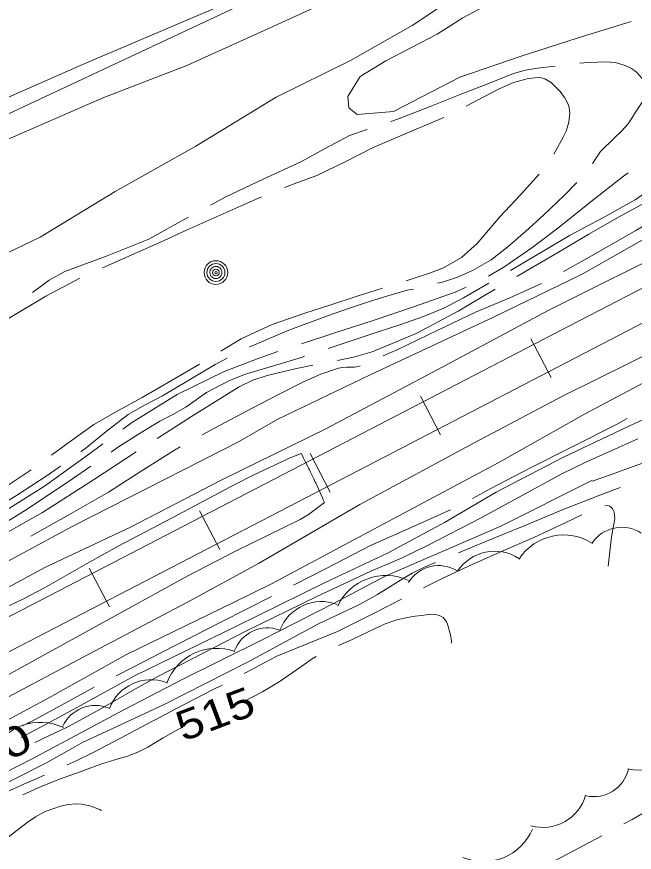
# Model space of a CAD drawing. Extents: x 2361284 to 2366480, y 6976556 to 6985346.
# Drawn here: x 2364083.1 to 2364182.3, y 6978587.5 to 6978721.9 of the extents above; entities that cross this region are included whole.
import ezdxf
from ezdxf.enums import TextEntityAlignment as Align

# ---------------------------------------------------------------- set-up
doc = ezdxf.new("R2010")
doc.units = 0
doc.header["$LTSCALE"] = 1.9
for name, color, linetype, lineweight in [('12', 7, 'Continuous', 13), ('13', 7, 'Continuous', 13), ('15', 7, 'Continuous', 13), ('16', 7, 'Continuous', 13), ('20', 7, 'Continuous', 13), ('22', 7, 'Continuous', 13), ('29', 7, 'Continuous', 13), ('3', 7, 'Continuous', 13), ('4', 7, 'Continuous', 13)]:
    doc.layers.add(name, color=color, linetype=linetype, lineweight=lineweight)

msp = doc.modelspace()

# ---------------------------------------------------------------- linework, layer by layer
at = {"layer": '12'}
msp.add_lwpolyline([(2364083.777, 6978605.938), (2364089.996, 6978609.258), (2364102.074, 6978615.943), (2364118.289, 6978623.778), (2364132.662, 6978630.886), (2364142.678, 6978635.59), (2364151.802, 6978640.557), (2364160.135, 6978645.426), (2364170.933, 6978651.06), (2364182.343, 6978656.449), (2364195.668, 6978662.296), (2364208.403, 6978668.106), (2364217.26, 6978673.692)], dxfattribs=at)
at = {"layer": '13'}
for points in [[(2364316.907, 6978749.303), (2364313.473, 6978747.58), (2364304.173, 6978743.362), (2364291.676, 6978737.742), (2364273.995, 6978728.114), (2364260.412, 6978721.104), (2364242.99, 6978711.738), (2364226.685, 6978703.713), (2364208.352, 6978694.457), (2364190.207, 6978685.475), (2364168.479, 6978674.628), (2364150.769, 6978665.128), (2364132.758, 6978655.598), (2364116.035, 6978647.397), (2364101.248, 6978639.726), (2364087.697, 6978633.368), (2364076.324, 6978627.239), (2364064.329, 6978621.474), (2364055.005, 6978617.546), (2364048.402, 6978614.643), (2364040.227, 6978611.065), (2364032.027, 6978606.637)], [(2364320.846, 6978741.031), (2364317.59, 6978739.54), (2364310.146, 6978735.718), (2364301.969, 6978731.13), (2364295.123, 6978727.505), (2364285.873, 6978722.206), (2364276.399, 6978717.277), (2364262.941, 6978709.688), (2364252.425, 6978703.897), (2364240.292, 6978696.902), (2364227.251, 6978690.538), (2364214.992, 6978683.981), (2364202.477, 6978677.171), (2364186.695, 6978668.74), (2364170.8, 6978660.879), (2364156.681, 6978653.385), (2364138.204, 6978643.408), (2364121.923, 6978633.953), (2364110.521, 6978627.734), (2364094.521, 6978619.291), (2364075.604, 6978609.261), (2364063.636, 6978602.807), (2364048.497, 6978595.203), (2364040.513, 6978590.407)], [(2364271.539, 6978729.88), (2364252.804, 6978721.862), (2364234.916, 6978714.261), (2364211.606, 6978701.559), (2364192.514, 6978691.066), (2364173.944, 6978680.48), (2364159.698, 6978673.554), (2364139.756, 6978664.253), (2364125.053, 6978657.144), (2364118.707, 6978653.514), (2364104.067, 6978646.083), (2364092.095, 6978639.919), (2364081.369, 6978634.147), (2364067.98, 6978626.579), (2364056.145, 6978619.746), (2364051.183, 6978617.739), (2364044.277, 6978615.273), (2364038.087, 6978612.114), (2364031.238, 6978607.659)], [(2364138.539, 6978726.956), (2364125.687, 6978720.973), (2364110.391, 6978714.068), (2364097.079, 6978708.901), (2364080.018, 6978701.528), (2364064.988, 6978693.054), (2364045.989, 6978686.494), (2364033.041, 6978680.931), (2364026.961, 6978677.803), (2364011.93, 6978671.578), (2364001.985, 6978665.624), (2363992.21, 6978660.91)], [(2364301.264, 6978725.323), (2364290.21, 6978719.437), (2364278.454, 6978712.585), (2364264.992, 6978705.397), (2364245.94, 6978695.915), (2364230.683, 6978687.12), (2364211.127, 6978677.274), (2364191.552, 6978667.116), (2364174.308, 6978657.983), (2364160.441, 6978650.12), (2364138.84, 6978638.584), (2364124.005, 6978630.643), (2364117.793, 6978627.583), (2364100.712, 6978619.27), (2364088.197, 6978612.321), (2364078.027, 6978606.854), (2364068.178, 6978601.63), (2364061.939, 6978598.331), (2364053.285, 6978594.358)], [(2364162.082, 6978725.72), (2364154.781, 6978721.75), (2364150.646, 6978719.1), (2364142.365, 6978714.802), (2364138.239, 6978712.302), (2364136.289, 6978709.064), (2364136.417, 6978707.245), (2364137.797, 6978706.158), (2364143.642, 6978706.683), (2364154.292, 6978712.175), (2364163.979, 6978715.497), (2364173.133, 6978718.454), (2364181.838, 6978721.117)], [(2363990.169, 6978666.251), (2363998.65, 6978670.392), (2364009.081, 6978675.623), (2364018.458, 6978680.122), (2364028.992, 6978685.072), (2364041.462, 6978690.48), (2364054.213, 6978696.613), (2364060.696, 6978699.584), (2364070.861, 6978704.321), (2364081.28, 6978708.761), (2364093.539, 6978714.197), (2364108.997, 6978720.775), (2364118.22, 6978724.732)], [(2364081.556, 6978683.942), (2364086.852, 6978686.462), (2364098.903, 6978693.806), (2364111.844, 6978701.071), (2364124.741, 6978708.964), (2364136.704, 6978714.878), (2364146.632, 6978720.522), (2364151.203, 6978723.546)], [(2364085.975, 6978605.119), (2364091.252, 6978607.64), (2364096.11, 6978610.302), (2364102.506, 6978614.002), (2364105.745, 6978615.778), (2364119.886, 6978623.063), (2364131.284, 6978628.642), (2364139.965, 6978632.715), (2364144.887, 6978634.801), (2364149.194, 6978636.885), (2364157.696, 6978641.273), (2364170.57, 6978648.306), (2364174.622, 6978650.313), (2364182.896, 6978653.974)], [(2364128.756, 6978651.649), (2364127.023, 6978650.923), (2364121.043, 6978648.145), (2364118.102, 6978646.657), (2364108.162, 6978641.352), (2364099.355, 6978636.728), (2364094.254, 6978633.892), (2364087.5, 6978630.023), (2364084.066, 6978628.193), (2364079.15, 6978625.868), (2364072.514, 6978622.938), (2364069.23, 6978621.401), (2364057.753, 6978615.772), (2364045.141, 6978609.641), (2364041.156, 6978607.882), (2364038.449, 6978606.828), (2364032.964, 6978604.875)], [(2364132.51, 6978643.754), (2364132.322, 6978644.192), (2364132.196, 6978644.484), (2364131.941, 6978645.066), (2364131.812, 6978645.356), (2364131.552, 6978645.936), (2364131.289, 6978646.514), (2364131.111, 6978646.899), (2364130.992, 6978647.155), (2364130.753, 6978647.667), (2364130.541, 6978648.114), (2364130.398, 6978648.412), (2364130.302, 6978648.61), (2364130.108, 6978649.005), (2364129.962, 6978649.301), (2364129.864, 6978649.497), (2364129.666, 6978649.89), (2364129.366, 6978650.478), (2364129.164, 6978650.869), (2364129.029, 6978651.129), (2364128.756, 6978651.649)], [(2364042.263, 6978586.203), (2364043.908, 6978584.609), (2364047.058, 6978584.569), (2364053.349, 6978586.588), (2364060.968, 6978589.991), (2364067.641, 6978593.895), (2364073.966, 6978596.585), (2364085.53, 6978602.525), (2364100.286, 6978610.396), (2364109.839, 6978615.367), (2364122.301, 6978621.526), (2364134.064, 6978627.578), (2364142.174, 6978631.826), (2364160.898, 6978639.943), (2364175.49, 6978647.282)], [(2364132.51, 6978643.754), (2364129.975, 6978641.846), (2364128.617, 6978641.037), (2364118.094, 6978635.866), (2364110.581, 6978631.956), (2364099.946, 6978626.123), (2364087.183, 6978619.062), (2364076.129, 6978612.946), (2364071.277, 6978610.53), (2364064.642, 6978607.635), (2364061.344, 6978606.145), (2364054.101, 6978602.645), (2364050.514, 6978600.812), (2364046.548, 6978598.514), (2364043.999, 6978596.829), (2364039.046, 6978593.223)], [(2364040.349, 6978584.585), (2364041.366, 6978583.823), (2364044.159, 6978583.48), (2364051.251, 6978584.218), (2364058.424, 6978587.217), (2364064.973, 6978590.539), (2364070.255, 6978593.529), (2364077.415, 6978596.588), (2364087.737, 6978601.836), (2364093.655, 6978605.152), (2364106.768, 6978611.257), (2364120.233, 6978618.106), (2364131.446, 6978624.173), (2364138.156, 6978627.337)], [(2364085.443, 6978608.535), (2364085.327, 6978608.477), (2364085.172, 6978608.4), (2364085.094, 6978608.361), (2364085.052, 6978608.34), (2364084.969, 6978608.299), (2364084.885, 6978608.259), (2364084.829, 6978608.232), (2364084.792, 6978608.214), (2364084.742, 6978608.19), (2364084.717, 6978608.178), (2364084.661, 6978608.152), (2364084.549, 6978608.099), (2364084.324, 6978607.993), (2364084.212, 6978607.94), (2364084.1, 6978607.887), (2364084.044, 6978607.86), (2364083.96, 6978607.82)]]:
    msp.add_lwpolyline(points, dxfattribs=at)
at = {"layer": '15'}
for points in [[(2364197.95, 6978602.084), (2364196.131, 6978600.987), (2364182.008, 6978592.752), (2364180.665, 6978592.029)], [(2364177.133, 6978590.145), (2364167.322, 6978584.922), (2364159.379, 6978580.935)]]:
    msp.add_lwpolyline(points, dxfattribs=at)
at = {"layer": '16'}
for centre, radius, start, end in [((2364180.301, 6978634.068), 5.694, 56.68024, 146.68024), ((2364170.953, 6978629.982), 8.546, 56.83182, 146.83182), ((2364159.881, 6978628.785), 7.125, 56.83182, 146.83182), ((2364150.902, 6978627.908), 5.694, 58.58081, 148.58081), ((2364142.408, 6978623.465), 8.546, 64.9872, 154.9872), ((2364132.035, 6978620.682), 7.125, 69.29215, 159.29215), ((2364123.379, 6978617.874), 5.694, 69.94529, 159.94529), ((2364115.203, 6978611.748), 8.546, 69.94529, 159.94529), ((2364104.636, 6978608.109), 7.125, 69.5711, 159.5711), ((2364095.663, 6978605.407), 5.694, 66.6985, 156.6985), ((2364086.849, 6978599.843), 8.546, 64.33074, 154.33074), ((2364183.152, 6978609.24), 8.546, 257.31447, 347.31447), ((2364175.829, 6978602.116), 5.694, 257.31447, 347.31447), ((2364167.646, 6978598.596), 7.125, 254.08649, 344.08649), ((2364158.072, 6978594.518), 8.546, 247.21802, 337.21802)]:
    msp.add_arc(centre, radius, start, end, dxfattribs=at)
at = {"layer": '20'}
for points in [[(2364175.634, 6978698.297), (2364176.916, 6978700.229), (2364179.145, 6978702.431), (2364180.285, 6978703.502), (2364181.314, 6978704.681), (2364181.945, 6978705.587), (2364182.546, 6978706.533), (2364183.68, 6978708.304), (2364184.181, 6978709.189), (2364184.583, 6978710.073), (2364184.631, 6978710.313), (2364184.599, 6978710.533), (2364184.435, 6978710.911), (2364183.524, 6978712.043), (2364182.766, 6978712.906), (2364182.352, 6978713.262), (2364181.869, 6978713.577), (2364180.845, 6978714.067), (2364179.28, 6978714.543), (2364177.689, 6978714.677), (2364174.22, 6978714.494), (2364173.561, 6978714.418)], [(2364169.585, 6978713.98), (2364166.787, 6978713.654), (2364164.83, 6978713.325), (2364162.935, 6978712.757), (2364158.761, 6978711.117), (2364154.597, 6978709.478), (2364149.526, 6978707.469), (2364144.444, 6978705.471), (2364143.168, 6978705.049)], [(2364169.38, 6978699.788), (2364169.685, 6978700.271), (2364170.914, 6978702.542), (2364171.355, 6978703.497), (2364171.811, 6978704.961), (2364171.967, 6978706.413), (2364171.859, 6978707.302), (2364171.642, 6978707.96), (2364171.123, 6978708.915), (2364170.394, 6978709.868), (2364169.576, 6978710.75), (2364168.95, 6978711.314), (2364167.954, 6978711.935), (2364167.433, 6978712.1), (2364166.892, 6978712.155), (2364165.323, 6978711.99), (2364162.929, 6978711.307), (2364160.629, 6978710.305), (2364156.003, 6978707.871), (2364155.276, 6978707.504)], [(2364151.703, 6978705.71), (2364151.355, 6978705.537), (2364145.856, 6978703.204), (2364140.358, 6978700.852), (2364135.839, 6978698.579), (2364131.3, 6978696.346), (2364127.634, 6978695.001), (2364126.099, 6978694.435)], [(2364139.38, 6978703.763), (2364136.569, 6978702.786), (2364132.618, 6978700.728), (2364128.72, 6978698.571), (2364122.686, 6978695.754), (2364116.652, 6978692.935), (2364114.194, 6978691.592)], [(2364145.672, 6978679.431), (2364149.591, 6978680.679), (2364151.653, 6978681.498), (2364154.547, 6978683.186), (2364157.076, 6978685.4), (2364158.915, 6978687.548), (2364160.714, 6978689.705), (2364164.011, 6978693.265), (2364167.041, 6978696.555)], [(2364181.359, 6978696.801), (2364180.584, 6978696.264), (2364175.403, 6978692.174), (2364170.262, 6978688.026), (2364165.882, 6978684.744), (2364161.381, 6978681.621), (2364158.885, 6978680.157)], [(2364150.716, 6978679.039), (2364151.475, 6978679.217), (2364153.927, 6978680.03), (2364156.328, 6978681.053), (2364159.3, 6978682.811), (2364162.01, 6978684.907), (2364164.916, 6978687.415), (2364167.753, 6978689.982), (2364171.123, 6978693.193), (2364173.084, 6978695.233)], [(2364186.533, 6978695.271), (2364182.441, 6978692.431), (2364177.258, 6978689.562), (2364172.044, 6978686.752), (2364166.524, 6978683.51), (2364162.416, 6978681.091)], [(2364195.218, 6978694.843), (2364190.325, 6978692.016), (2364182.587, 6978687.533), (2364175.187, 6978683.272), (2364170.93, 6978680.912)], [(2364122.382, 6978692.95), (2364119.125, 6978691.509), (2364114.306, 6978689.344), (2364110.462, 6978687.597), (2364106.629, 6978685.84), (2364100.126, 6978682.949), (2364096.84, 6978681.487)], [(2364110.683, 6978689.668), (2364110.474, 6978689.557), (2364104.316, 6978686.119), (2364097.591, 6978683.434), (2364090.795, 6978680.94), (2364088.268, 6978679.506), (2364085.577, 6978677.55)], [(2364093.195, 6978679.832), (2364087.722, 6978676.96), (2364082.015, 6978673.526), (2364078.397, 6978671.17), (2364074.88, 6978668.667), (2364073.383, 6978667.383), (2364071.333, 6978665.223), (2364070.153, 6978664.182)], [(2364158.966, 6978679.068), (2364154.869, 6978676.659), (2364151.725, 6978675.019), (2364148.458, 6978673.658), (2364144.649, 6978672.36), (2364140.841, 6978671.094), (2364134.909, 6978669.128), (2364133.124, 6978668.541)], [(2364115.858, 6978668.106), (2364116.007, 6978668.198), (2364119.129, 6978670.088), (2364124.139, 6978672.375), (2364129.342, 6978674.196), (2364133.558, 6978675.566), (2364137.775, 6978676.936), (2364141.863, 6978678.225)], [(2364120.451, 6978668.8), (2364120.501, 6978668.821), (2364126.777, 6978671.47), (2364133.154, 6978673.852), (2364136.364, 6978674.963), (2364139.583, 6978676.043), (2364142.684, 6978677.013), (2364145.807, 6978677.903), (2364146.127, 6978677.956), (2364146.456, 6978678.009), (2364146.825, 6978678.102)], [(2364155.303, 6978678.393), (2364153.55, 6978677.616), (2364146.982, 6978675.274), (2364140.372, 6978673.041), (2364133.862, 6978670.938), (2364128.828, 6978669.3)], [(2364167.418, 6978678.998), (2364162.298, 6978676.689), (2364156.821, 6978674.387), (2364150.619, 6978671.427), (2364144.416, 6978668.448), (2364141.966, 6978667.325)], [(2364093.361, 6978651.933), (2364093.937, 6978652.348), (2364097.43, 6978655.192), (2364100.995, 6978657.926), (2364103.72, 6978659.442), (2364106.466, 6978660.908), (2364110.712, 6978663.427), (2364114.958, 6978665.938), (2364116.878, 6978666.996)], [(2364125.04, 6978668.024), (2364121.849, 6978666.923), (2364116.409, 6978664.822), (2364108.834, 6978661.12), (2364101.657, 6978656.672), (2364100.117, 6978655.537)], [(2364129.327, 6978667.274), (2364128.978, 6978667.161), (2364124.332, 6978665.737), (2364119.674, 6978664.323), (2364117.153, 6978663.349), (2364113.571, 6978661.445), (2364110.223, 6978659.083)], [(2364088.636, 6978651.348), (2364091.247, 6978653.323), (2364095.469, 6978656.323), (2364099.328, 6978658.51), (2364103.208, 6978660.647), (2364108.062, 6978663.452), (2364112.448, 6978666.004)], [(2364138.281, 6978665.76), (2364138.142, 6978665.698), (2364137.333, 6978665.52), (2364136.053, 6978665.508), (2364135.414, 6978665.482), (2364134.795, 6978665.366), (2364131.934, 6978664.399), (2364129.166, 6978663.193), (2364125.126, 6978661.135), (2364121.114, 6978659.047), (2364114.736, 6978655.656), (2364112.846, 6978654.628)], [(2364110.223, 6978659.083), (2364108.154, 6978657.924), (2364106.065, 6978656.814), (2364102.644, 6978654.721), (2364099.265, 6978652.579), (2364098.231, 6978651.869)], [(2364181.195, 6978657.258), (2364179.354, 6978656.271), (2364172.467, 6978652.755), (2364165.559, 6978649.288), (2364159.28, 6978645.978), (2364156.316, 6978644.42)], [(2364096.899, 6978653.166), (2364094.615, 6978651.485), (2364087.523, 6978646.386), (2364081.906, 6978642.842), (2364076.248, 6978639.359), (2364073.565, 6978637.733)], [(2364109.344, 6978652.705), (2364108.399, 6978652.186), (2364103.081, 6978648.804), (2364097.783, 6978645.404), (2364091.407, 6978641.763), (2364085.319, 6978638.345)], [(2364175.53, 6978647.193), (2364178.481, 6978648.221), (2364181.421, 6978649.259), (2364186.114, 6978650.935), (2364188.725, 6978651.88)], [(2364066.068, 6978635.292), (2364071.509, 6978638.363), (2364074.731, 6978640.074), (2364077.955, 6978641.805), (2364083.007, 6978644.873), (2364087.937, 6978648.12), (2364090.102, 6978649.621)], [(2364094.943, 6978649.597), (2364092.032, 6978647.579), (2364084.738, 6978642.659), (2364078.872, 6978639.063), (2364072.956, 6978635.537), (2364071.325, 6978634.582)], [(2364061.302, 6978634.836), (2364064.018, 6978636.272), (2364067.354, 6978637.824), (2364070.658, 6978639.455), (2364075.917, 6978642.696), (2364081.065, 6978646.115), (2364084.096, 6978648.154), (2364085.378, 6978649.026)], [(2364154.079, 6978635.638), (2364158.312, 6978637.399), (2364164.607, 6978640.019), (2364170.914, 6978642.629), (2364176.792, 6978644.915), (2364180.031, 6978646.146)], [(2364177.568, 6978643.232), (2364177.948, 6978643.266), (2364178.188, 6978643.228), (2364178.359, 6978643.15), (2364178.601, 6978642.982), (2364178.803, 6978642.734), (2364179.068, 6978642.186), (2364179.162, 6978641.777), (2364179.188, 6978641.157), (2364179.114, 6978640.537), (2364178.885, 6978639.394), (2364178.666, 6978638.242), (2364178.388, 6978635.869), (2364178.111, 6978633.498)], [(2364152.773, 6978642.566), (2364146.46, 6978639.746), (2364139.926, 6978636.824), (2364132.771, 6978633.137), (2364127.547, 6978630.447)], [(2364148.462, 6978630.016), (2364151.14, 6978631.351), (2364155.759, 6978633.575), (2364160.956, 6978635.884), (2364166.175, 6978638.133), (2364171.194, 6978640.481), (2364173.872, 6978641.757)], [(2364138.156, 6978627.337), (2364139.609, 6978628.151), (2364141.051, 6978628.965), (2364144.77, 6978631.281), (2364146.64, 6978632.408), (2364148.601, 6978633.367), (2364150.384, 6978634.103)], [(2364123.995, 6978628.623), (2364115.972, 6978624.526), (2364106.329, 6978619.604), (2364101.642, 6978617.209), (2364099.064, 6978615.884)], [(2364119.611, 6978616.23), (2364120.726, 6978616.81), (2364122.806, 6978617.93), (2364124.886, 6978619.04), (2364129.747, 6978621.026), (2364134.638, 6978622.973), (2364140.599, 6978626.02), (2364144.889, 6978628.212)], [(2364095.521, 6978614.021), (2364091.203, 6978611.659), (2364085.443, 6978608.535)], [(2364091.18, 6978601.549), (2364092.603, 6978602.212), (2364095.47, 6978603.6), (2364099.719, 6978605.839), (2364103.958, 6978608.081), (2364106.247, 6978609.282), (2364108.545, 6978610.474), (2364114.636, 6978613.642), (2364116.059, 6978614.386)], [(2364075.012, 6978593.715), (2364076.363, 6978594.678), (2364077.785, 6978595.521), (2364083.741, 6978598.228), (2364087.535, 6978599.904)], [(2364079.025, 6978588.263), (2364081.054, 6978589.422), (2364083.507, 6978591.285), (2364084.717, 6978592.277), (2364086.059, 6978593.19), (2364087.651, 6978594.025), (2364090.093, 6978594.918), (2364091.33, 6978595.16), (2364092.569, 6978595.262), (2364093.46, 6978595.22), (2364094.802, 6978594.963), (2364096.107, 6978594.485), (2364096.408, 6978594.338), (2364096.71, 6978594.181)]]:
    msp.add_lwpolyline(points, dxfattribs=at)
at = {"layer": '22'}
for points in [[(2364187.735, 6978693.981), (2364187.377, 6978693.798), (2364180.185, 6978689.9), (2364175.013, 6978686.901), (2364169.851, 6978683.871), (2364163.426, 6978680.1)], [(2364159.975, 6978678.067), (2364154.009, 6978674.55), (2364147.263, 6978670.925), (2364140.18, 6978667.978), (2364137.188, 6978667.139), (2364134.603, 6978666.625)], [(2364130.68, 6978665.847), (2364128.046, 6978665.332), (2364123.307, 6978664.177), (2364121.002, 6978663.435), (2364118.822, 6978662.384), (2364111.167, 6978657.612), (2364105.641, 6978654.05)], [(2364102.282, 6978651.878), (2364095.414, 6978647.421), (2364087.193, 6978642.133), (2364080.837, 6978638.552), (2364078.43, 6978637.229)], [(2364134.789, 6978620.744), (2364136.87, 6978621.654), (2364139.568, 6978622.94), (2364142.286, 6978624.216), (2364144.17, 6978624.874), (2364146.117, 6978625.322), (2364147.116, 6978625.472), (2364148.115, 6978625.571), (2364149.663, 6978625.776), (2364150.433, 6978625.743), (2364150.824, 6978625.647), (2364151.206, 6978625.481), (2364151.588, 6978625.224), (2364152.064, 6978624.649), (2364152.318, 6978624.151), (2364152.764, 6978622.485), (2364152.901, 6978621.797), (2364152.934, 6978621.457), (2364152.937, 6978621.117)], [(2364119.335, 6978611.607), (2364119.455, 6978611.658), (2364119.574, 6978611.709), (2364122.55, 6978613.268), (2364125.424, 6978615.015), (2364128.861, 6978617.418), (2364130.569, 6978618.614), (2364131.206, 6978618.98)], [(2364084.035, 6978596.691), (2364086.972, 6978598.079), (2364090.091, 6978599.268), (2364093.23, 6978600.428), (2364094.994, 6978601.075), (2364096.758, 6978601.722), (2364098.812, 6978602.331), (2364100.868, 6978602.921), (2364102.511, 6978603.587), (2364104.113, 6978604.372), (2364106.579, 6978605.864), (2364109.086, 6978607.279), (2364109.554, 6978607.484), (2364109.733, 6978607.565)]]:
    msp.add_lwpolyline(points, dxfattribs=at)
at = {"layer": '29'}
for p, q in [((2364165.711, 6978670.071), (2364168.942, 6978663.851)), ((2364147.969, 6978660.852), (2364151.188, 6978654.643)), ((2364130.215, 6978651.633), (2364133.444, 6978645.423)), ((2364112.462, 6978642.413), (2364115.691, 6978636.203)), ((2364094.719, 6978633.195), (2364097.948, 6978626.984))]:
    msp.add_line(p, q, dxfattribs=at)
for points in [[(2363926.674, 6978544.462), (2363964.107, 6978564.229), (2364001.623, 6978583.856), (2364042.853, 6978605.198), (2364084.062, 6978626.542), (2364128.694, 6978649.718), (2364173.346, 6978672.904), (2364214.057, 6978694.031), (2364254.768, 6978715.12), (2364294.894, 6978735.833), (2364335.019, 6978756.535), (2364356.186, 6978767.468), (2364377.374, 6978778.399), (2364394.91, 6978787.357), (2364412.486, 6978796.234)], [(2363929.006, 6978540.034), (2363966.429, 6978559.8), (2364003.925, 6978579.417), (2364045.145, 6978600.751), (2364086.354, 6978622.094), (2364130.996, 6978645.279), (2364175.648, 6978668.465), (2364216.349, 6978689.584), (2364257.061, 6978710.672), (2364297.185, 6978731.384), (2364337.311, 6978752.087), (2364358.478, 6978763.02), (2364379.656, 6978773.951), (2364397.172, 6978782.897), (2364414.739, 6978791.766)]]:
    msp.add_lwpolyline(points, dxfattribs=at)
at = {"layer": '3'}
msp.add_lwpolyline([(2364277.747, 6978798.494), (2364265.377, 6978793.347), (2364259.251, 6978790.637), (2364239.026, 6978781.314), (2364228.947, 6978776.586), (2364213.87, 6978769.405), (2364191.365, 6978758.465), (2364161.385, 6978743.824), (2364146.339, 6978736.62), (2364078.247, 6978704.681), (2364006.908, 6978671.621), (2363983.987, 6978660.696), (2363968.777, 6978653.267), (2363938.462, 6978638.188)], dxfattribs=at)
for radius in [20778.456, 20777.496]:
    msp.add_arc((2372981.712, 6959966.989), radius, 115.24593, 115.78543, dxfattribs=at)
at = {"layer": '4'}
for radius in [1.9, 1.442, 0.539, 0.192]:
    msp.add_circle((2364115.078, 6978680.751), radius, dxfattribs=at)
for start, end in [(174.71552, 185.96556), (163.46611, 174.71615), (185.96287, 197.21291), (152.21535, 163.46538), (197.21479, 208.46483), (140.96646, 152.21649), (129.71376, 140.96379), (118.46406, 129.71409), (107.21593, 118.46597), (95.96582, 107.21585), (84.71553, 95.96557), (73.46552, 84.71555), (62.21535, 73.46538), (50.96397, 62.214), (39.71588, 50.96591), (28.46656, 39.7166), (17.21479, 28.46483), (332.21419, 343.46422), (5.96345, 17.21348), (343.46611, 354.71615), (354.71553, 5.96557), (208.46822, 219.71826), (219.71376, 230.96379), (230.96397, 242.214), (242.21812, 253.46815), (253.46258, 264.71261), (264.71553, 275.96557), (275.96582, 287.21585), (287.21593, 298.46597), (298.46406, 309.71409), (309.71589, 320.96592), (320.96646, 332.21649)]:
    msp.add_arc((2364115.078, 6978680.751), 0.973, start, end, dxfattribs=at)

# ---------------------------------------------------------------- texts
at = {"layer": '12', "width": 1.2}
msp.add_text(' 515 ', height=4.8, rotation=20.616, dxfattribs=at).set_placement((2364115.787, 6978607.5), align=Align.CENTER)
at = {"layer": '13', "width": 1.35}
msp.add_text(' 520 ', height=4.8, rotation=27.168, dxfattribs=at).set_placement((2364079.618, 6978600.994), align=Align.CENTER)

doc.saveas('drawing.dxf')
